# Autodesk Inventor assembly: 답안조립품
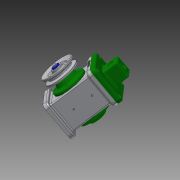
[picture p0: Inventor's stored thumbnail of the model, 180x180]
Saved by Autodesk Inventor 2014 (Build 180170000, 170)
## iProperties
Created: 2017-08
Part Number: 답안조립품
Document SubType Name: Assembly
Designer: 601-14
Author: 601-14
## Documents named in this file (18)
- C:\Users\601-14\Desktop\470808V1005\답안조립품.iam
- C:\Users\601-14\Desktop\470808V1005\본체.ipt
- C:\Users\601-14\Desktop\470808V1005\편심축.ipt
- C:\Users\601-14\Desktop\470808V1005\와셔 4x16.ipt
- C:\Users\601-14\Desktop\470808V1005\볼트 M4 x 10.ipt
- C:\Users\601-14\Desktop\470808V1005\베어링 17 x 40 x 12.ipt
- C:\Users\601-14\Desktop\470808V1005\키 4 x 4 x 12.ipt
- C:\Users\601-14\Desktop\470808V1005\뒤커버.ipt
- C:\Users\601-14\Desktop\470808V1005\앞커버.ipt
- C:\Users\601-14\Desktop\470808V1005\볼트 M4 x 8.ipt
- C:\Users\601-14\Desktop\470808V1005\슬라이더.ipt
- C:\Users\601-14\Desktop\470808V1005\클레비스 핀 6 x 22.ipt
- 클레비스 핀 6 x 22.ipt
- C:\Users\601-14\Desktop\470808V1005\링크.ipt
- C:\Users\601-14\Desktop\470808V1005\E-링.ipt
- C:\Users\601-14\Desktop\470808V1005\덮개.ipt
- C:\Users\601-14\Desktop\470808V1005\V-벨트풀리.ipt
- C:\Users\601-14\Desktop\470808V1005\오일 실 17 30 8.ipt
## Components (2 placed, 2 different names)
1. E-링:1 — 각도:8
2. V-벨트풀리:1 — 각도:13
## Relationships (2: Angle 2)
- 각도:8 [Angle]: E-링:1
- 각도:13 [Angle]: V-벨트풀리:1
